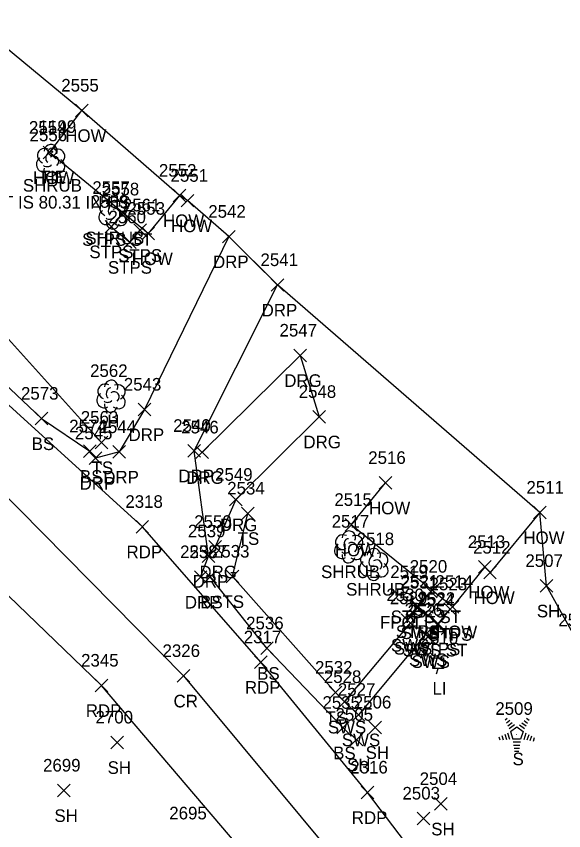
# Model space of a CAD drawing. Extents: x 1638344 to 1639591, y 610835 to 612202.
# Drawn here: x 1638879.7 to 1638966.6, y 611582.6 to 611711.9 of the extents above; entities that cross this region are included whole.
import ezdxf

# ---------------------------------------------------------------- set-up
doc = ezdxf.new("R2010")
doc.units = 0
for name, color, linetype in [('C_A', 7, 'Continuous'), ('C_C', 7, 'Continuous'), ('C_I', 7, 'Continuous'), ('CBP', 7, 'Continuous'), ('L_A', 7, 'Continuous'), ('L_I', 7, 'Continuous'), ('L_TIC', 7, 'Continuous'), ('LBC', 7, 'Continuous'), ('LBF', 7, 'Continuous'), ('LELB', 7, 'Continuous'), ('LFP', 7, 'Continuous'), ('LSH', 7, 'Continuous'), ('LSOGP', 7, 'Continuous'), ('LTC', 7, 'Continuous'), ('LTD', 7, 'Continuous'), ('P_A', 7, 'Continuous'), ('P_I', 7, 'Continuous'), ('P_TIC', 7, 'Continuous'), ('PET', 7, 'Continuous'), ('PRC', 7, 'Continuous'), ('R_A', 7, 'Continuous'), ('R_I', 7, 'Continuous'), ('R_TIC', 7, 'Continuous'), ('RDG', 7, 'Continuous'), ('RDP', 7, 'Continuous'), ('RSW', 7, 'Continuous'), ('U_A', 7, 'Continuous'), ('U_I', 7, 'Continuous'), ('ULP', 7, 'Continuous')]:
    doc.layers.add(name, color=color, linetype=linetype)

msp = doc.modelspace()

# ---------------------------------------------------------------- linework, layer by layer
at = {"layer": 'CBP'}
for radius in [0.625, 0.0833]:
    msp.add_circle((1638885.42, 611690.36), radius, dxfattribs=at)
at = {"layer": 'L_TIC'}
for points in [[(1638889.13, 611695.93), (1638891.13, 611697.93)], [(1638891.13, 611695.93), (1638889.13, 611697.93)], [(1638884, 611689.24), (1638886, 611691.24)], [(1638886, 611689.24), (1638884, 611691.24)], [(1638904.62, 611682.42), (1638906.62, 611684.42)], [(1638906.62, 611682.42), (1638904.62, 611684.42)], [(1638905.9, 611681.62), (1638907.9, 611683.61)], [(1638907.9, 611681.62), (1638905.9, 611683.61)], [(1638895.54, 611679.45), (1638897.54, 611681.45)], [(1638897.54, 611679.45), (1638895.54, 611681.45)], [(1638893.81, 611677.48), (1638895.81, 611679.48)], [(1638895.81, 611677.48), (1638893.81, 611679.48)], [(1638898.37, 611676.91), (1638900.37, 611678.91)], [(1638900.37, 611676.91), (1638898.37, 611678.91)], [(1638899.64, 611676.38), (1638901.64, 611678.38)], [(1638901.64, 611676.38), (1638899.64, 611678.38)], [(1638896.75, 611675.02), (1638898.75, 611677.02)], [(1638898.75, 611675.02), (1638896.75, 611677.02)], [(1638882.74, 611647.03), (1638884.74, 611649.03)], [(1638884.74, 611647.03), (1638882.74, 611649.03)], [(1638892.27, 611643.22), (1638894.27, 611645.22)], [(1638894.27, 611643.22), (1638892.27, 611645.22)], [(1638890.39, 611641.84), (1638892.39, 611643.84)], [(1638892.39, 611641.84), (1638890.39, 611643.84)], [(1638937.3, 611636.84), (1638939.3, 611638.83)], [(1638939.3, 611636.84), (1638937.3, 611638.83)], [(1638915.45, 611631.98), (1638917.45, 611633.98)], [(1638917.45, 611631.98), (1638915.45, 611633.98)], [(1638961.79, 611632.12), (1638963.79, 611634.12)], [(1638963.79, 611632.12), (1638961.79, 611634.12)], [(1638931.88, 611630.17), (1638933.88, 611632.17)], [(1638933.88, 611630.17), (1638931.88, 611632.17)], [(1638953.04, 611623.49), (1638955.04, 611625.49)], [(1638955.04, 611623.49), (1638953.04, 611625.49)], [(1638953.88, 611622.59), (1638955.88, 611624.59)], [(1638955.88, 611622.59), (1638953.88, 611624.59)], [(1638909.47, 611621.92), (1638911.47, 611623.92)], [(1638911.47, 611621.92), (1638909.47, 611623.92)], [(1638913.03, 611621.97), (1638915.03, 611623.97)], [(1638915.03, 611621.97), (1638913.03, 611623.97)], [(1638944.49, 611619.57), (1638946.49, 611621.57)], [(1638946.49, 611619.57), (1638944.49, 611621.57)], [(1638962.82, 611620.48), (1638964.82, 611622.48)], [(1638964.82, 611620.48), (1638962.82, 611622.48)], [(1638942.42, 611617.21), (1638944.42, 611619.21)], [(1638944.42, 611617.21), (1638942.42, 611619.21)], [(1638947.92, 611617.17), (1638949.92, 611619.17)], [(1638949.92, 611617.17), (1638947.92, 611619.17)], [(1638947.55, 611616.77), (1638949.55, 611618.77)], [(1638949.55, 611616.77), (1638947.55, 611618.77)], [(1638945.66, 611614.46), (1638947.66, 611616.46)], [(1638947.66, 611614.46), (1638945.66, 611616.46)], [(1638918.5, 611610.59), (1638920.5, 611612.58)], [(1638920.5, 611610.59), (1638918.5, 611612.58)], [(1638929.38, 611603.55), (1638931.38, 611605.55)], [(1638931.38, 611603.55), (1638929.38, 611605.55)], [(1638930.56, 611597.97), (1638932.56, 611599.97)], [(1638932.56, 611597.97), (1638930.56, 611599.97)], [(1638935.66, 611598.02), (1638937.66, 611600.02)], [(1638937.66, 611598.02), (1638935.66, 611600.02)], [(1638894.73, 611595.64), (1638896.73, 611597.64)], [(1638896.73, 611595.64), (1638894.73, 611597.64)], [(1638932.71, 611596.07), (1638934.71, 611598.07)], [(1638934.71, 611596.07), (1638932.71, 611598.07)], [(1638886.29, 611588.01), (1638888.29, 611590.01)], [(1638888.29, 611588.01), (1638886.29, 611590.01)], [(1638946.06, 611585.88), (1638948.06, 611587.88)], [(1638948.06, 611585.88), (1638946.06, 611587.88)], [(1638943.33, 611583.57), (1638945.33, 611585.57)], [(1638945.33, 611583.57), (1638943.33, 611585.57)]]:
    msp.add_lwpolyline(points, dxfattribs=at)
at = {"layer": 'LBC'}
for points in [[(1638906.9, 611682.61), (1638905.62, 611683.42), (1638900.64, 611677.38), (1638885, 611690.24), (1638890.13, 611696.93)], [(1638962.78, 611633.12), (1638954.88, 611623.59), (1638954.04, 611624.48), (1638948.92, 611618.17), (1638932.88, 611631.17), (1638938.3, 611637.83)]]:
    msp.add_lwpolyline(points, dxfattribs=at)
at = {"layer": 'LBF'}
for points in [[(1638896.54, 611680.45), (1638894.81, 611678.48), (1638897.75, 611676.02), (1638899.37, 611677.91)], [(1638945.49, 611620.57), (1638943.42, 611618.21), (1638946.66, 611615.46), (1638948.55, 611617.77)]]:
    msp.add_lwpolyline(points, dxfattribs=at)
at = {"layer": 'LELB'}
for points in [[(1638873.21, 611711.87), (1638857.7, 611692.04), (1638852.16, 611680.33), (1638857.5, 611671.46), (1638870.87, 611660.14), (1638883.74, 611648.03), (1638891.39, 611642.84)], [(1638893.27, 611644.22), (1638875.11, 611664.31), (1638860.57, 611677.05), (1638859.03, 611684.69), (1638875.95, 611708.59)], [(1638930.38, 611604.55), (1638914.03, 611622.97), (1638916.45, 611632.98)], [(1638931.56, 611598.97), (1638919.5, 611611.58), (1638910.47, 611622.92)]]:
    msp.add_lwpolyline(points, dxfattribs=at)
at = {"layer": 'LFP'}
for radius in [0.625, 0.0833]:
    msp.add_circle((1638941.77, 611619.7), radius, dxfattribs=at)
at = {"layer": 'LSH'}
for p, q in [((1638885.15, 611689.04), (1638885.15, 611689.04)), ((1638885.15, 611689.04), (1638885.15, 611689.04)), ((1638895.06, 611680.69), (1638895.06, 611680.69)), ((1638895.06, 611680.69), (1638895.06, 611680.69)), ((1638932.45, 611627.71), (1638932.45, 611627.71)), ((1638932.45, 611627.71), (1638932.45, 611627.71)), ((1638936.42, 611624.93), (1638936.42, 611624.93)), ((1638936.42, 611624.93), (1638936.42, 611624.93))]:
    msp.add_line(p, q, dxfattribs=at)
for centre in [(1638885.2, 611690.47), (1638895.1, 611682.13), (1638932.5, 611629.14), (1638936.46, 611626.37)]:
    msp.add_arc(centre, 1.05, 335.5272, 180.9563, dxfattribs=at)
for centre, major_axis, ratio, start_param, end_param in [((1638884.36, 611689.7), (1.21, -0.51), 0.895232, 1.570796, 4.712389), ((1638884.95, 611689.49), (-0.208, -0.792), 0.645439, 3.141593, 6.283185), ((1638886.2, 611689.62), (-1.14, -0.48), 0.949671, 1.570796, 4.712389), ((1638884.07, 611688.33), (0.58, -1.04), 0.959034, 3.141593, 6.283185), ((1638885.65, 611688.87), (-0.5, 0.667), 0.989748, 3.141593, 6.283185), ((1638886.15, 611688.2), (-1.09, 0.79), 0.841452, 1.570796, 4.712389), ((1638885.15, 611687.54), (0.26, 1.06), 0.942809, 1.570796, 4.712389), ((1638884.7, 611688.29), (-0.625, -0.083), 0.423636, 0, 3.141593), ((1638894.26, 611681.36), (1.21, -0.51), 0.895232, 1.570796, 4.712389), ((1638896.1, 611681.28), (-1.14, -0.48), 0.949671, 1.570796, 4.712389), ((1638893.97, 611679.98), (0.58, -1.04), 0.959034, 3.141593, 6.283185), ((1638894.85, 611681.15), (-0.208, -0.792), 0.645439, 3.141593, 6.283185), ((1638895.56, 611680.53), (-0.5, 0.667), 0.989748, 3.141593, 6.283185), ((1638894.6, 611679.94), (-0.625, -0.083), 0.423636, 0, 3.141593), ((1638896.06, 611679.86), (-1.09, 0.79), 0.841452, 1.570796, 4.712389), ((1638895.06, 611679.19), (0.26, 1.06), 0.942809, 1.570796, 4.712389), ((1638931.66, 611628.37), (1.21, -0.51), 0.895232, 1.570796, 4.712389), ((1638933.49, 611628.29), (-1.14, -0.48), 0.949671, 1.570796, 4.712389), ((1638931.37, 611627), (0.58, -1.04), 0.959034, 3.141593, 6.283185), ((1638932.24, 611628.17), (-0.208, -0.792), 0.645439, 3.141593, 6.283185), ((1638932.95, 611627.54), (-0.5, 0.667), 0.989748, 3.141593, 6.283185), ((1638931.99, 611626.96), (-0.625, -0.083), 0.423636, 0, 3.141593), ((1638933.45, 611626.87), (-1.09, 0.79), 0.841452, 1.570796, 4.712389), ((1638935.63, 611625.6), (1.21, -0.51), 0.895232, 1.570796, 4.712389), ((1638937.46, 611625.52), (-1.14, -0.48), 0.949671, 1.570796, 4.712389), ((1638932.45, 611626.21), (0.26, 1.06), 0.942809, 1.570796, 4.712389), ((1638936.21, 611625.39), (-0.208, -0.792), 0.645439, 3.141593, 6.283185), ((1638936.92, 611624.77), (-0.5, 0.667), 0.989748, 3.141593, 6.283185), ((1638935.33, 611624.23), (0.58, -1.04), 0.959034, 3.141593, 6.283185), ((1638935.96, 611624.18), (-0.625, -0.083), 0.423636, 0, 3.141593), ((1638937.42, 611624.1), (-1.09, 0.79), 0.841452, 1.570796, 4.712389), ((1638936.42, 611623.44), (0.26, 1.06), 0.942809, 1.570796, 4.712389)]:
    msp.add_ellipse(centre, major_axis=major_axis, ratio=ratio, start_param=start_param, end_param=end_param, dxfattribs=at)
at = {"layer": 'LSOGP'}
msp.add_lwpolyline([(1639180.86, 611428.14), (1639147.48, 611423.38), (1639131.91, 611444.98), (1639113.36, 611469.05), (1639093.12, 611490.67), (1639071.05, 611509.19), (1639055.5, 611526.42), (1639050.5, 611524.84), (1639039.27, 611539.22), (1639036.19, 611539.99), (1638995.83, 611580.21), (1638989.8, 611583.83), (1638969.06, 611612.07), (1638963.82, 611621.48), (1638962.78, 611633.12), (1638921.16, 611669.23), (1638917.31, 611673.07), (1638913.45, 611676.9), (1638906.9, 611682.61), (1638905.62, 611683.42), (1638890.13, 611696.93), (1638875.95, 611708.59)], dxfattribs=at)
at = {"layer": 'LTC'}
for p, q in [((1638957.26, 611600.22), (1638957.62, 611600.47)), ((1638957.47, 611599.75), (1638958, 611600.14)), ((1638957.68, 611599.29), (1638958.39, 611599.8)), ((1638959.92, 611599.76), (1638960.6, 611599.27)), ((1638960.29, 611600.11), (1638960.84, 611599.71)), ((1638960.66, 611600.46), (1638961.08, 611600.15)), ((1638957.89, 611598.82), (1638958.77, 611599.46)), ((1638958.12, 611598.37), (1638959.13, 611599.1)), ((1638958.12, 611598.37), (1638958.5, 611597.17)), ((1638959.13, 611599.1), (1638960.13, 611598.37)), ((1638959.55, 611599.41), (1638960.36, 611598.82)), ((1638960.13, 611598.37), (1638959.73, 611597.17)), ((1638956.3, 611597.5), (1638956.45, 611597.03)), ((1638956.75, 611597.71), (1638956.96, 611597.06)), ((1638957.21, 611597.93), (1638957.48, 611597.09)), ((1638957.66, 611598.15), (1638957.99, 611597.13)), ((1638959.73, 611597.17), (1638958.5, 611597.17)), ((1638960.56, 611598.1), (1638960.22, 611597.06)), ((1638961.01, 611597.85), (1638960.72, 611596.97)), ((1638961.45, 611597.6), (1638961.21, 611596.87)), ((1638961.9, 611597.35), (1638961.71, 611596.78)), ((1638959.7, 611596.67), (1638958.55, 611596.67)), ((1638959.61, 611596.17), (1638958.62, 611596.17)), ((1638959.53, 611595.67), (1638958.7, 611595.67)), ((1638959.44, 611595.17), (1638958.77, 611595.17))]:
    msp.add_line(p, q, dxfattribs=at)
at = {"layer": 'LTD'}
msp.add_line((1638894.75, 611651.63), (1638894.75, 611651.63), dxfattribs=at)
msp.add_line((1638894.75, 611651.63), (1638894.75, 611651.63), dxfattribs=at)
msp.add_arc((1638894.79, 611653.07), 1.05, 335.5272, 180.9563, dxfattribs=at)
for centre, major_axis, ratio, start_param, end_param in [((1638893.96, 611652.3), (1.21, -0.51), 0.895232, 1.570796, 4.712389), ((1638894.54, 611652.09), (-0.208, -0.792), 0.645439, 3.141593, 6.283185), ((1638895.79, 611652.22), (-1.14, -0.48), 0.949671, 1.570796, 4.712389), ((1638893.66, 611650.93), (0.58, -1.04), 0.959034, 3.141593, 6.283185), ((1638895.25, 611651.47), (-0.5, 0.667), 0.989748, 3.141593, 6.283185), ((1638895.75, 611650.8), (-1.09, 0.79), 0.841452, 1.570796, 4.712389), ((1638894.75, 611650.13), (0.26, 1.06), 0.942809, 1.570796, 4.712389), ((1638894.29, 611650.88), (-0.625, -0.083), 0.423636, 0, 3.141593)]:
    msp.add_ellipse(centre, major_axis=major_axis, ratio=ratio, start_param=start_param, end_param=end_param, dxfattribs=at)
at = {"layer": 'P_TIC'}
for points in [[(1638898.73, 611629.86), (1638900.73, 611631.86)], [(1638900.73, 611629.86), (1638898.73, 611631.86)], [(1638917.51, 611608.36), (1638919.51, 611610.36)], [(1638919.51, 611608.36), (1638917.51, 611610.36)], [(1638905.24, 611606.2), (1638907.24, 611608.2)], [(1638907.24, 611606.2), (1638905.24, 611608.2)], [(1638892.27, 611604.67), (1638894.27, 611606.67)], [(1638894.27, 611604.67), (1638892.27, 611606.67)], [(1638934.46, 611587.7), (1638936.46, 611589.7)], [(1638936.46, 611587.7), (1638934.46, 611589.7)]]:
    msp.add_lwpolyline(points, dxfattribs=at)
at = {"layer": 'PET'}
for points in [[(1639148.64, 611331.08), (1639142.07, 611329.18), (1639135.7, 611328.74), (1639125.69, 611331.15), (1639119.18, 611334.88), (1639114.19, 611340.57), (1639098.76, 611361.78), (1639080.32, 611387.34), (1639061.62, 611413.48), (1639039.15, 611444.22), (1639014.34, 611480.36), (1638988.41, 611516.9), (1638963.39, 611551.85), (1638935.46, 611588.7), (1638918.51, 611609.36), (1638899.73, 611630.86), (1638874.41, 611653.86), (1638846.55, 611674.47), (1638833.14, 611682.54), (1638823.86, 611689.16)], [(1639117.36, 611283.38), (1639114.12, 611301.89), (1639095.51, 611328.5), (1639070.51, 611363.26), (1639041.38, 611404.69), (1639011.58, 611446.4), (1638984.33, 611485.15), (1638954.17, 611527.5), (1638934.33, 611554.77), (1638918.88, 611575.58), (1638893.27, 611605.67), (1638868.12, 611629.84), (1638836.66, 611652.85), (1638812.43, 611667.64)]]:
    msp.add_lwpolyline(points, dxfattribs=at)
at = {"layer": 'PRC'}
msp.add_lwpolyline([(1638818.79, 611678.84), (1638843.98, 611663.35), (1638876.44, 611637.39), (1638906.24, 611607.19), (1638934.14, 611573.69), (1638965.31, 611531.43), (1638998.82, 611484.34), (1639033.82, 611434.48), (1639068.01, 611386.3), (1639093.94, 611350.49), (1639111.89, 611325.38), (1639129.23, 611302.77)], dxfattribs=at)
at = {"layer": 'R_TIC'}
for points in [[(1638912.45, 611675.9), (1638914.45, 611677.9)], [(1638914.45, 611675.9), (1638912.45, 611677.9)], [(1638920.16, 611668.23), (1638922.16, 611670.23)], [(1638922.16, 611668.23), (1638920.16, 611670.23)], [(1638923.75, 611657.05), (1638925.75, 611659.05)], [(1638925.75, 611657.05), (1638923.75, 611659.05)], [(1638899.05, 611648.48), (1638901.05, 611650.47)], [(1638901.05, 611648.48), (1638899.05, 611650.47)], [(1638926.79, 611647.31), (1638928.79, 611649.31)], [(1638928.79, 611647.31), (1638926.79, 611649.31)], [(1638895.04, 611641.73), (1638897.04, 611643.73)], [(1638897.04, 611641.73), (1638895.04, 611643.73)], [(1638906.97, 611641.92), (1638908.97, 611643.92)], [(1638908.97, 611641.92), (1638906.97, 611643.92)], [(1638908.2, 611641.67), (1638910.2, 611643.67)], [(1638910.2, 611641.67), (1638908.2, 611643.67)], [(1638891.29, 611640.74), (1638893.29, 611642.74)], [(1638893.29, 611640.74), (1638891.29, 611642.74)], [(1638913.54, 611634.16), (1638915.54, 611636.16)], [(1638915.54, 611634.16), (1638913.54, 611636.16)], [(1638910.3, 611626.68), (1638912.3, 611628.68)], [(1638912.3, 611626.68), (1638910.3, 611628.68)], [(1638909.22, 611625.19), (1638911.22, 611627.19)], [(1638911.22, 611625.19), (1638909.22, 611627.19)], [(1638907.98, 611621.88), (1638909.98, 611623.88)], [(1638909.98, 611621.88), (1638907.98, 611623.88)], [(1638942.35, 611617.04), (1638944.35, 611619.03)], [(1638944.35, 611617.04), (1638942.35, 611619.03)], [(1638940.79, 611615.05), (1638942.79, 611617.05)], [(1638942.79, 611615.05), (1638940.79, 611617.05)], [(1638941.27, 611614.58), (1638943.27, 611616.58)], [(1638943.27, 611614.58), (1638941.27, 611616.58)], [(1638945.53, 611614.28), (1638947.53, 611616.28)], [(1638947.53, 611614.28), (1638945.53, 611616.28)], [(1638943.66, 611612.74), (1638945.66, 611614.74)], [(1638945.66, 611612.74), (1638943.66, 611614.74)], [(1638944.06, 611612.46), (1638946.06, 611614.46)], [(1638946.06, 611612.46), (1638944.06, 611614.46)], [(1638930.78, 611602.06), (1638932.78, 611604.06)], [(1638932.78, 611602.06), (1638930.78, 611604.06)], [(1638933, 611600.03), (1638935, 611602.03)], [(1638935, 611600.03), (1638933, 611602.03)]]:
    msp.add_lwpolyline(points, dxfattribs=at)
at = {"layer": 'RDG'}
msp.add_lwpolyline([(1638909.2, 611642.67), (1638924.75, 611658.05), (1638927.79, 611648.31), (1638914.54, 611635.16), (1638911.3, 611627.68)], dxfattribs=at)
at = {"layer": 'RDP'}
msp.add_lwpolyline([(1638908.98, 611622.88), (1638910.22, 611626.19), (1638907.97, 611642.92), (1638921.16, 611669.23), (1638913.45, 611676.9), (1638900.05, 611649.47), (1638896.04, 611642.73), (1638892.29, 611641.74)], dxfattribs=at)
at = {"layer": 'RSW'}
msp.add_lwpolyline([(1638946.53, 611615.28), (1638945.06, 611613.46), (1638944.65, 611613.74), (1638934, 611601.03), (1638931.77, 611603.06), (1638942.27, 611615.57), (1638941.79, 611616.05), (1638943.35, 611618.04)], dxfattribs=at)
at = {"layer": 'ULP'}
for p, q in [((1638945.82, 611608.36), (1638945.82, 611610.03)), ((1638945.82, 611610.03), (1638947.49, 611610.03)), ((1638946.82, 611610.86), (1638946.66, 611610.03)), ((1638947.49, 611610.03), (1638947.49, 611608.36)), ((1638946.66, 611609.2), (1638946.66, 611609.2)), ((1638947.49, 611608.36), (1638945.82, 611608.36)), ((1638946.41, 611607.53), (1638946.66, 611608.36))]:
    msp.add_line(p, q, dxfattribs=at)

# ---------------------------------------------------------------- texts
at = {"layer": 'C_A'}
msp.add_text('TIE', height=2, dxfattribs=at).set_placement((1638883.49, 611685.36))
at = {"layer": 'C_C'}
msp.add_text('TIE DIST IS 80.31 IN HS', height=2, dxfattribs=at).set_placement((1638868.27, 611681.36))
at = {"layer": 'C_I'}
msp.add_text('1199', height=2, dxfattribs=at).set_placement((1638883.28, 611693.36))
at = {"layer": 'L_A'}
for s, p in [('HOW', (1638887.51, 611691.93)), ('HOW', (1638882.39, 611685.24)), ('SHRUB', (1638880.78, 611684.04)), ('HOW', (1638903.01, 611678.42)), ('HOW', (1638904.28, 611677.61)), ('STPS ST', (1638890.18, 611675.45)), ('SHRUB', (1638890.69, 611675.69)), ('STPS', (1638891.33, 611673.48)), ('STPS', (1638895.89, 611672.91)), ('HOW', (1638898.03, 611672.38)), ('STPS', (1638894.27, 611671.02)), ('H', (1638894.18, 611646.63)), ('BS', (1638882.18, 611643.03)), ('TS', (1638891.68, 611639.22)), ('BS', (1638889.83, 611637.84)), ('HOW', (1638935.69, 611632.83)), ('TS', (1638914.86, 611627.98)), ('HOW', (1638960.17, 611628.12)), ('HOW', (1638930.27, 611626.17)), ('SHRUB', (1638928.08, 611622.71)), ('SHRUB', (1638932.05, 611619.93)), ('HOW', (1638951.42, 611619.48)), ('HOW', (1638952.26, 611618.59)), ('BS', (1638908.91, 611617.92)), ('TS', (1638912.44, 611617.97)), ('SH', (1638962.31, 611616.48)), ('FPOLE', (1638937.43, 611614.7)), ('STPS ST', (1638939.13, 611615.57)), ('STPS', (1638939.94, 611613.21)), ('HOW', (1638946.31, 611613.17)), ('STPS', (1638945.07, 611612.77)), ('STPS', (1638943.18, 611610.46)), ('BS', (1638917.94, 611606.58)), ('TS', (1638928.79, 611599.55)), ('BS', (1638930, 611593.97)), ('SH', (1638935.15, 611594.02)), ('S', (1638958.45, 611593.01)), ('SH', (1638894.22, 611591.64)), ('SH', (1638932.2, 611592.07)), ('SH', (1638885.78, 611584.01)), ('SH', (1638945.55, 611581.88))]:
    msp.add_text(s, height=2, dxfattribs=at).set_placement(p)
at = {"layer": 'L_I'}
for s, p in [('2555', (1638886.87, 611699.93)), ('2554', (1638881.74, 611693.24)), ('2556', (1638881.84, 611692.04)), ('2552', (1638902.36, 611686.42)), ('2551', (1638904.2, 611685.61)), ('2557', (1638891.8, 611683.69)), ('2558', (1638893.28, 611683.45)), ('2559', (1638891.55, 611681.48)), ('2561', (1638896.63, 611680.91)), ('2553', (1638897.38, 611680.38)), ('2560', (1638894.35, 611679.02)), ('2562', (1638891.44, 611654.63)), ('2573', (1638880.48, 611651.03)), ('2563', (1638889.96, 611647.22)), ('2574', (1638888.13, 611645.84)), ('2516', (1638935.56, 611640.83)), ('2534', (1638913.19, 611635.98)), ('2511', (1638960.66, 611636.12)), ('2515', (1638930.19, 611634.17)), ('2517', (1638929.76, 611630.71)), ('2518', (1638933.72, 611627.94)), ('2513', (1638951.35, 611627.48)), ('2512', (1638952.19, 611626.59)), ('2537', (1638907.21, 611625.92)), ('2533', (1638910.77, 611625.97)), ('2520', (1638942.14, 611623.57)), ('2507', (1638960.49, 611624.48)), ('2519', (1638939.06, 611622.7)), ('2521', (1638940.73, 611621.21)), ('2514', (1638946.23, 611621.17)), ('2523', (1638945.29, 611620.77)), ('2522', (1638943.4, 611618.46)), ('2536', (1638916.19, 611614.58)), ('2508', (1638965.72, 611615.07)), ('2532', (1638927.12, 611607.55)), ('2535', (1638928.3, 611601.97)), ('2506', (1638933.27, 611602.02)), ('2509', (1638955.72, 611601.01)), ('2700', (1638892.3, 611599.64)), ('2505', (1638930.37, 611600.07)), ('2699', (1638883.98, 611592.01)), ('2504', (1638943.72, 611589.88)), ('2503', (1638940.99, 611587.57)), ('2695', (1638904, 611584.42))]:
    msp.add_text(s, height=2, dxfattribs=at).set_placement(p)
at = {"layer": 'LTC'}
msp.add_text('.', height=1.04, rotation=270, dxfattribs=at).set_placement((1638959.01, 611598.11))
at = {"layer": 'P_A'}
for s, p in [('RDP', (1638897.22, 611625.86)), ('RDP', (1638916, 611604.36)), ('CR', (1638904.68, 611602.19)), ('RDP', (1638890.76, 611600.67)), ('RDP', (1638932.95, 611583.7))]:
    msp.add_text(s, height=2, dxfattribs=at).set_placement(p)
at = {"layer": 'P_I'}
for s, p in [('2318', (1638897.03, 611633.86)), ('2317', (1638915.82, 611612.36)), ('2326', (1638902.93, 611610.19)), ('2345', (1638890.01, 611608.67)), ('2316', (1638932.71, 611591.7))]:
    msp.add_text(s, height=2, dxfattribs=at).set_placement(p)
at = {"layer": 'R_A'}
for s, p in [('DRP', (1638910.94, 611671.9)), ('DRP', (1638918.65, 611664.23)), ('DRG', (1638922.24, 611653.05)), ('DRP', (1638897.54, 611644.47)), ('DRG', (1638925.28, 611643.31)), ('DRP', (1638893.53, 611637.73)), ('DRP', (1638905.45, 611637.92)), ('DRG', (1638906.69, 611637.67)), ('DRP', (1638889.78, 611636.74)), ('DRG', (1638912.03, 611630.16)), ('DRG', (1638908.79, 611622.68)), ('DRP', (1638907.71, 611621.19)), ('DRP', (1638906.47, 611617.88)), ('SWS', (1638940.72, 611613.04)), ('SWS', (1638939.16, 611611.05)), ('SWS', (1638939.64, 611610.57)), ('SWS ST', (1638941.03, 611610.28)), ('SWS', (1638942.03, 611608.74)), ('SWS', (1638942.43, 611608.46)), ('SWS', (1638929.15, 611598.06)), ('SWS', (1638931.37, 611596.03))]:
    msp.add_text(s, height=2, dxfattribs=at).set_placement(p)
at = {"layer": 'R_I'}
for s, p in [('2542', (1638910.19, 611679.9)), ('2541', (1638918.47, 611672.23)), ('2547', (1638921.49, 611661.05)), ('2543', (1638896.79, 611652.47)), ('2548', (1638924.53, 611651.31)), ('2544', (1638892.78, 611645.73)), ('2540', (1638904.62, 611645.92)), ('2546', (1638905.89, 611645.67)), ('2545', (1638889.03, 611644.74)), ('2549', (1638911.27, 611638.16)), ('2550', (1638907.95, 611630.68)), ('2539', (1638906.96, 611629.19)), ('2538', (1638905.72, 611625.88)), ('2531', (1638940.66, 611621.04)), ('2530', (1638938.44, 611619.05)), ('2529', (1638939, 611618.57)), ('2524', (1638943.27, 611618.28)), ('2526', (1638941.34, 611616.74)), ('2525', (1638941.8, 611616.46)), ('2528', (1638928.52, 611606.06)), ('2527', (1638930.74, 611604.03))]:
    msp.add_text(s, height=2, dxfattribs=at).set_placement(p)
at = {"layer": 'U_A'}
msp.add_text('LI', height=2, dxfattribs=at).set_placement((1638945.76, 611604.2))
at = {"layer": 'U_I'}
msp.add_text('2510', height=2, dxfattribs=at).set_placement((1638943.88, 611612.2))

doc.saveas('drawing.dxf')
